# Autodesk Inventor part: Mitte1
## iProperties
Created: 2005-01
Part Number: Mitte1
Document SubType Name: Modeling
Designer: Administrator
Manufacturer: Standard
Standards Organization: Custom
Material: Stainless Steel, 440C
Author: Administrator
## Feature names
1. Revolution1
2. Extrusion1
3. Extrusion2
